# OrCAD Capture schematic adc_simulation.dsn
size A
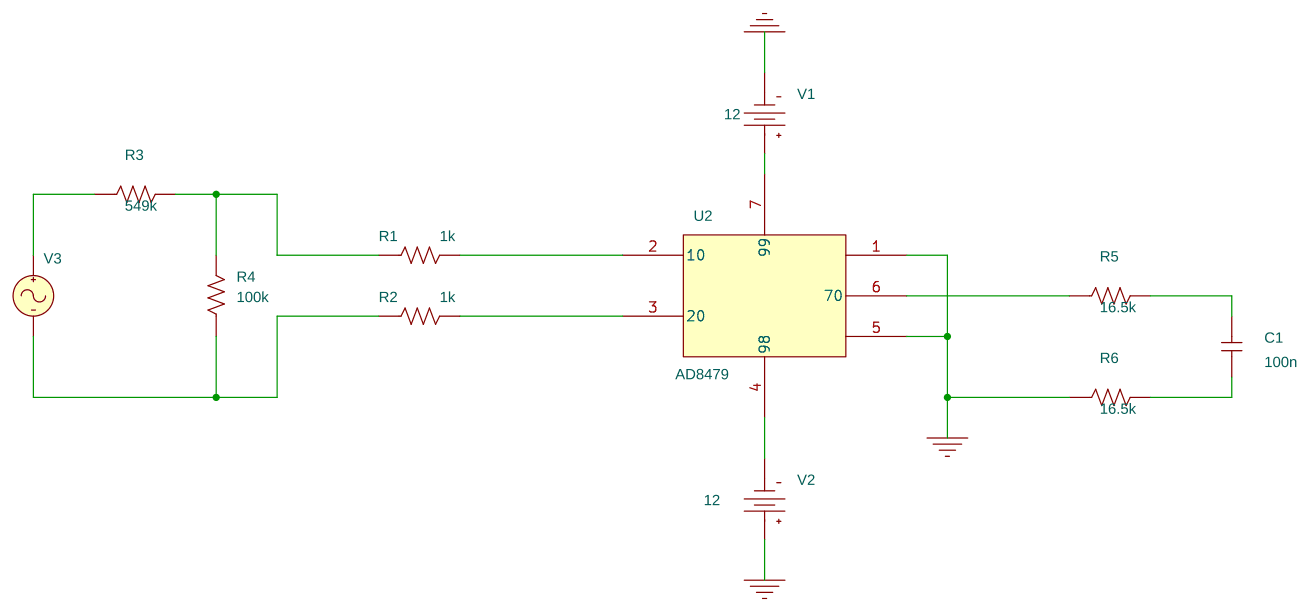
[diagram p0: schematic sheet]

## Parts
C1  100n  [cap196]
R1  1k  [AXRC05]
R2  1k  [AXRC05]
R3  549k  [AXRC05]
R4  100k  [AXRC05]
R5  16.5k  [AXRC05]
R6  16.5k  [AXRC05]
U2  AD8479
V1  VDC
V2  VDC
V3  VAC

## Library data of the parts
C1 = C
R1-R6 = R
U2 = AD8479_3
V1 V2 = VDC: DC: 12
V3 = VAC

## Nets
0: R6.1 U2.1 U2.5 V1.1(-) V2.0(+)
N01199: U2.4(98) V2.1(-)
N01426: R1.1 R3.2 R4.2
N01450: R2.1 R4.1 V3.2(-)
N01459: R3.1 V3.1(+)
N01528: C1.2 R5.2
N01535: C1.1 R6.2
N02597: R5.1 U2.6(70)
N02615: R1.2 U2.2(10)
N02619: R2.2 U2.3(20)
N02756: U2.7(99) V1.0(+)
